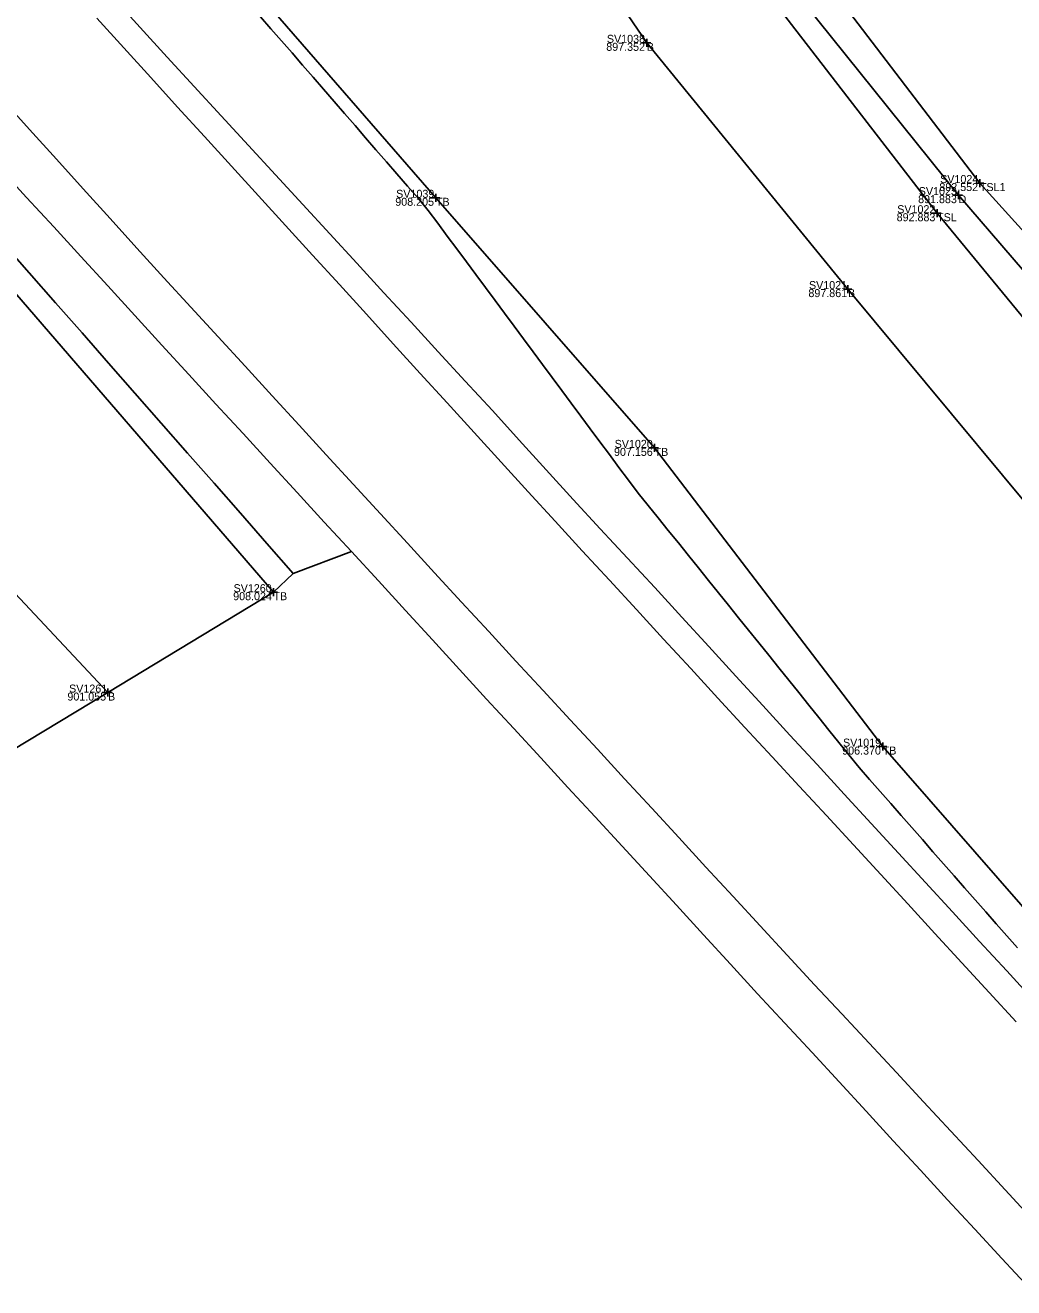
# Model space of a CAD drawing. Extents: x 1918148 to 1919797, y 624701 to 627089.
# Drawn here: x 1919035.3 to 1919158.7, y 625353.2 to 625511 of the extents above; entities that cross this region are included whole.
import ezdxf

# ---------------------------------------------------------------- set-up
doc = ezdxf.new("R2010")
doc.units = 0
for name, color, linetype in [('DR_X_Ditch', 7, 'Continuous'), ('DT_X_Terrain_Boundary', 7, 'Continuous'), ('PM_X_Edge_Line', 7, 'Continuous'), ('PV_X_Shoulder_Aggregate', 7, 'Continuous'), ('RD_X_Concrete_Pad', 7, 'Continuous'), ('SV_X_Break_Lines', 7, 'Continuous'), ('SV_X_Shot_Marker', 7, 'Continuous'), ('SV_X_Text_Comment', 7, 'Continuous'), ('SV_X_Text_Elevation', 7, 'Continuous'), ('SV_X_Text_Name', 7, 'Continuous'), ('SV_X_Toe_of_Slope', 7, 'Continuous'), ('SV_X_Top_of_Bank', 7, 'Continuous')]:
    doc.layers.add(name, color=color, linetype=linetype)

msp = doc.modelspace()

# ---------------------------------------------------------------- linework, layer by layer
at = {"layer": 'DR_X_Ditch'}
msp.add_lwpolyline([(1919219.02, 625407.66), (1919187.13, 625448.73), (1919151.86, 625489.75), (1919129.02, 625518.23), (1919101.03, 625555.91), (1919077.07, 625591.12), (1919056.34, 625619.29)], dxfattribs=at)
at = {"layer": 'DT_X_Terrain_Boundary'}
msp.add_lwpolyline([(1919029.61, 625417.96), (1919045.66, 625427.6), (1919066.32, 625440.14), (1919068.79, 625442.49), (1919076.05, 625445.23), (1919079.43, 625441.55), (1919082.8, 625437.86), (1919086.18, 625434.17), (1919089.55, 625430.48), (1919092.93, 625426.79), (1919096.31, 625423.11), (1919099.7, 625419.43), (1919103.08, 625415.75), (1919106.47, 625412.07), (1919109.86, 625408.4), (1919113.25, 625404.72), (1919116.63, 625401.04), (1919120.01, 625397.35), (1919123.38, 625393.66), (1919126.77, 625389.98), (1919130.16, 625386.31), (1919133.56, 625382.64), (1919136.95, 625378.97), (1919140.33, 625375.29), (1919143.71, 625371.6), (1919147.09, 625367.92), (1919150.49, 625364.24), (1919153.88, 625360.57), (1919157.27, 625356.9), (1919160.68, 625353.24)], dxfattribs=at)
at = {"layer": 'PM_X_Edge_Line'}
for points in [[(1919044.26, 625511.85), (1919047.62, 625508.15), (1919050.99, 625504.45), (1919054.35, 625500.75), (1919057.72, 625497.06), (1919061.08, 625493.36), (1919064.45, 625489.66), (1919067.82, 625485.97), (1919071.18, 625482.27), (1919074.55, 625478.57), (1919077.92, 625474.88), (1919081.28, 625471.18), (1919084.65, 625467.48), (1919088.02, 625463.79), (1919091.38, 625460.09), (1919094.75, 625456.39), (1919098.12, 625452.7), (1919101.49, 625449), (1919104.87, 625445.32), (1919108.26, 625441.64), (1919111.64, 625437.96), (1919115.03, 625434.28), (1919118.41, 625430.6), (1919121.8, 625426.92), (1919125.19, 625423.25), (1919128.58, 625419.58), (1919131.97, 625415.9), (1919135.37, 625412.23), (1919138.76, 625408.56), (1919142.15, 625404.88), (1919145.53, 625401.19), (1919148.9, 625397.51), (1919152.28, 625393.82), (1919155.66, 625390.14), (1919159.04, 625386.45)], [(1919032.51, 625501.67), (1919035.86, 625497.96), (1919039.21, 625494.24), (1919042.56, 625490.53), (1919045.91, 625486.82), (1919049.26, 625483.11), (1919052.64, 625479.43), (1919056.02, 625475.74), (1919059.4, 625472.06), (1919062.78, 625468.37), (1919066.16, 625464.68), (1919069.53, 625461), (1919072.91, 625457.31), (1919076.29, 625453.63), (1919079.67, 625449.94), (1919083.05, 625446.25), (1919086.43, 625442.57), (1919089.81, 625438.88), (1919093.2, 625435.21), (1919096.59, 625431.54), (1919099.98, 625427.86), (1919103.37, 625424.19), (1919106.76, 625420.51), (1919110.15, 625416.84), (1919113.54, 625413.16), (1919116.92, 625409.48), (1919120.31, 625405.8), (1919123.7, 625402.12), (1919127.08, 625398.44), (1919130.47, 625394.77), (1919133.88, 625391.1), (1919137.28, 625387.44), (1919140.68, 625383.78), (1919144.09, 625380.11), (1919147.49, 625376.45), (1919150.89, 625372.79), (1919154.29, 625369.12), (1919157.69, 625365.45), (1919161.08, 625361.78)]]:
    msp.add_lwpolyline(points, dxfattribs=at)
at = {"layer": 'PV_X_Shoulder_Aggregate'}
for points in [[(1919068.79, 625442.49), (1919065.49, 625446.24), (1919062.19, 625450), (1919058.9, 625453.75), (1919055.6, 625457.51), (1919052.3, 625461.26), (1919049.01, 625465.02), (1919045.71, 625468.77), (1919042.42, 625472.53), (1919039.12, 625476.29), (1919035.82, 625480.04), (1919032.53, 625483.8), (1919029.14, 625487.48), (1919025.75, 625491.14), (1919022.35, 625494.81), (1919018.95, 625498.47), (1919015.55, 625502.14), (1919012.16, 625505.8), (1919008.76, 625509.47), (1919005.36, 625513.13)], [(1919064.7, 625512.04), (1919066.01, 625510.53), (1919067.33, 625509.02), (1919068.64, 625507.51), (1919069.95, 625506), (1919071.26, 625504.49), (1919072.57, 625502.98), (1919073.88, 625501.47), (1919075.19, 625499.96), (1919076.5, 625498.44), (1919077.81, 625496.93), (1919079.12, 625495.42), (1919080.43, 625493.91), (1919081.74, 625492.4), (1919083.06, 625490.89), (1919084.37, 625489.38), (1919085.64, 625487.85), (1919086.83, 625486.24), (1919088.02, 625484.63), (1919089.21, 625483.03), (1919090.41, 625481.42), (1919091.6, 625479.82), (1919092.79, 625478.21), (1919093.98, 625476.6), (1919095.17, 625475), (1919096.36, 625473.39), (1919097.55, 625471.79), (1919098.74, 625470.18), (1919099.93, 625468.57), (1919101.12, 625466.97), (1919102.31, 625465.36), (1919103.5, 625463.75), (1919104.69, 625462.15), (1919105.88, 625460.54), (1919107.07, 625458.94), (1919108.26, 625457.33), (1919109.45, 625455.72), (1919110.64, 625454.12), (1919111.87, 625452.53), (1919113.12, 625450.98), (1919114.37, 625449.42), (1919115.62, 625447.86), (1919116.88, 625446.3), (1919118.13, 625444.74), (1919119.38, 625443.18), (1919120.64, 625441.62), (1919121.89, 625440.06), (1919123.14, 625438.51), (1919124.39, 625436.95), (1919125.65, 625435.39), (1919126.9, 625433.83), (1919128.15, 625432.27), (1919129.4, 625430.71), (1919130.66, 625429.15), (1919131.91, 625427.6), (1919133.16, 625426.04), (1919134.42, 625424.48), (1919135.67, 625422.92), (1919136.92, 625421.36), (1919138.17, 625419.8), (1919139.43, 625418.25), (1919140.75, 625416.75), (1919142.07, 625415.24), (1919143.39, 625413.74), (1919144.71, 625412.23), (1919146.02, 625410.73), (1919147.34, 625409.23), (1919148.66, 625407.72), (1919149.98, 625406.22), (1919151.3, 625404.71), (1919152.61, 625403.21), (1919153.93, 625401.71), (1919155.25, 625400.2), (1919156.57, 625398.7), (1919157.89, 625397.2), (1919159.2, 625395.69)]]:
    msp.add_lwpolyline(points, dxfattribs=at)
at = {"layer": 'RD_X_Concrete_Pad'}
for points in [[(1919046.34, 625514.42), (1919049.69, 625510.71), (1919053.05, 625507), (1919056.43, 625503.32), (1919059.81, 625499.64), (1919063.19, 625495.95), (1919066.58, 625492.28), (1919069.97, 625488.6), (1919073.36, 625484.92), (1919076.74, 625481.24), (1919080.12, 625477.56), (1919083.51, 625473.88), (1919086.89, 625470.19), (1919090.27, 625466.51), (1919093.65, 625462.83), (1919097.01, 625459.12), (1919100.36, 625455.41), (1919103.72, 625451.71), (1919107.12, 625448.04), (1919110.52, 625444.38), (1919113.92, 625440.71), (1919117.3, 625437.03), (1919120.68, 625433.34), (1919124.06, 625429.66), (1919127.44, 625425.97), (1919130.81, 625422.28), (1919134.19, 625418.6), (1919137.57, 625414.92), (1919140.96, 625411.23), (1919144.34, 625407.55), (1919147.72, 625403.87), (1919151.11, 625400.19), (1919154.49, 625396.51), (1919157.87, 625392.82), (1919161.25, 625389.13)], [(1919032.12, 625493.14), (1919035.49, 625489.45), (1919038.88, 625485.77), (1919042.27, 625482.1), (1919045.65, 625478.41), (1919049.01, 625474.71), (1919052.38, 625471.01), (1919055.75, 625467.32), (1919059.13, 625463.64), (1919062.52, 625459.96), (1919065.9, 625456.28), (1919069.28, 625452.6), (1919072.67, 625448.91), (1919076.05, 625445.23), (1919079.43, 625441.55), (1919082.8, 625437.86), (1919086.18, 625434.17), (1919089.55, 625430.48), (1919092.93, 625426.79), (1919096.31, 625423.11), (1919099.7, 625419.43), (1919103.08, 625415.75), (1919106.47, 625412.07), (1919109.86, 625408.4), (1919113.25, 625404.72), (1919116.63, 625401.04), (1919120.01, 625397.35), (1919123.38, 625393.66), (1919126.77, 625389.98), (1919130.16, 625386.31), (1919133.56, 625382.64), (1919136.95, 625378.97), (1919140.33, 625375.29), (1919143.71, 625371.6), (1919147.09, 625367.92), (1919150.49, 625364.24), (1919153.88, 625360.57), (1919157.27, 625356.9), (1919160.68, 625353.24)]]:
    msp.add_lwpolyline(points, dxfattribs=at)
at = {"layer": 'SV_X_Break_Lines'}
for points in [[(1919045.66, 625427.6), (1919011.53, 625464.07), (1918983.19, 625498.78), (1918965.77, 625524.18), (1918940.24, 625565.26), (1918931.64, 625587.04), (1918915.78, 625618.09), (1918902.81, 625643.72), (1918894.51, 625661.89), (1918884.61, 625712.49), (1918865.54, 625771.79)], [(1919206.86, 625400.05), (1919170.29, 625439.2), (1919138.05, 625478.01), (1919112.93, 625508.78), (1919087.56, 625546), (1919063.33, 625584.96), (1919048.27, 625604.54), (1919031.79, 625617.49), (1919020.42, 625620.88), (1919013.82, 625627.54), (1919010.2, 625639.42), (1919006.75, 625653.62), (1919000.26, 625672.97)]]:
    msp.add_lwpolyline(points, dxfattribs=at)
at = {"layer": 'SV_X_Shot_Marker'}
for p, q in [((1919112.93, 625509.28), (1919112.93, 625508.28)), ((1919112.43, 625508.78), (1919113.43, 625508.78)), ((1919112.93, 625508.78), (1919112.93, 625508.78)), ((1919154.52, 625491.76), (1919154.52, 625490.76)), ((1919151.86, 625490.25), (1919151.86, 625489.25)), ((1919154.02, 625491.26), (1919155.02, 625491.26)), ((1919154.52, 625491.26), (1919154.52, 625491.26)), ((1919086.1, 625489.42), (1919087.1, 625489.42)), ((1919086.6, 625489.92), (1919086.6, 625488.92)), ((1919086.6, 625489.42), (1919086.6, 625489.42)), ((1919151.36, 625489.75), (1919152.36, 625489.75)), ((1919151.86, 625489.75), (1919151.86, 625489.75)), ((1919148.68, 625487.49), (1919149.68, 625487.49)), ((1919149.18, 625487.99), (1919149.18, 625486.99)), ((1919149.18, 625487.49), (1919149.18, 625487.49)), ((1919137.55, 625478.01), (1919138.55, 625478.01)), ((1919138.05, 625478.51), (1919138.05, 625477.51)), ((1919138.05, 625478.01), (1919138.05, 625478.01)), ((1919113.9, 625458.67), (1919113.9, 625457.67)), ((1919113.4, 625458.17), (1919114.4, 625458.17)), ((1919113.9, 625458.17), (1919113.9, 625458.17)), ((1919065.82, 625440.14), (1919066.82, 625440.14)), ((1919066.32, 625440.64), (1919066.32, 625439.64)), ((1919066.32, 625440.14), (1919066.32, 625440.14)), ((1919045.16, 625427.6), (1919046.16, 625427.6)), ((1919045.66, 625428.1), (1919045.66, 625427.1)), ((1919045.66, 625427.6), (1919045.66, 625427.6)), ((1919141.89, 625420.85), (1919142.89, 625420.85)), ((1919142.39, 625421.35), (1919142.39, 625420.35)), ((1919142.39, 625420.85), (1919142.39, 625420.85))]:
    msp.add_line(p, q, dxfattribs=at)
at = {"layer": 'SV_X_Toe_of_Slope'}
for points in [[(1919222.3, 625409.72), (1919190.71, 625451.22), (1919154.52, 625491.26), (1919132.35, 625520.35), (1919103.41, 625557.58), (1919078.28, 625592.14), (1919056.75, 625620.59)], [(1919214.66, 625404.51), (1919183.35, 625445.99), (1919149.18, 625487.49), (1919126.62, 625516.79), (1919098.28, 625553.96), (1919075.71, 625589.98), (1919054.68, 625616.82)]]:
    msp.add_lwpolyline(points, dxfattribs=at)
at = {"layer": 'SV_X_Top_of_Bank'}
for points in [[(1919180.03, 625377.77), (1919142.39, 625420.85), (1919113.9, 625458.17), (1919086.6, 625489.42), (1919057.39, 625523.08), (1919019.76, 625570.22), (1918998.07, 625602.27), (1918985.26, 625627.56), (1918968.39, 625668.03), (1918955.62, 625707.63), (1918947.9, 625739.17), (1918945.04, 625765.59), (1918947.37, 625785.94), (1918957.93, 625802.75), (1918975.61, 625809.21), (1918997.58, 625813.39), (1919030.67, 625814.44), (1919065.45, 625812.35), (1919111.29, 625808.54)], [(1919066.32, 625440.14), (1919029.78, 625482.47), (1919003.4, 625512.19), (1918983.32, 625538.26), (1918960.17, 625575.62), (1918948.94, 625596.56), (1918932.63, 625627.72), (1918922.22, 625652.79), (1918916.09, 625672.67), (1918901.24, 625716.64), (1918882.07, 625777.61)]]:
    msp.add_lwpolyline(points, dxfattribs=at)

# ---------------------------------------------------------------- texts
at = {"layer": 'SV_X_Text_Comment'}
for s, p in [('B', (1919112.93, 625507.78)), ('TSL1', (1919154.52, 625490.26)), ('TB', (1919086.6, 625488.42)), ('D', (1919151.86, 625488.75)), ('TSL', (1919149.18, 625486.49)), ('B', (1919138.05, 625477.01)), ('TB', (1919113.9, 625457.17)), ('TB', (1919066.32, 625439.14)), ('B', (1919045.66, 625426.6)), ('TB', (1919142.39, 625419.85))]:
    msp.add_text(s, height=1, dxfattribs=at).set_placement(p)
at = {"layer": 'SV_X_Text_Elevation'}
for s, p in [('897.352', (1919107.87, 625507.78)), ('892.552', (1919149.46, 625490.26)), ('908.205', (1919081.53, 625488.42)), ('891.883', (1919146.81, 625488.75)), ('892.883', (1919144.13, 625486.49)), ('897.861', (1919133.11, 625477.01)), ('907.156', (1919108.84, 625457.17)), ('908.024', (1919061.29, 625439.14)), ('901.055', (1919040.59, 625426.6)), ('906.370', (1919137.33, 625419.85))]:
    msp.add_text(s, height=1, dxfattribs=at).set_placement(p)
at = {"layer": 'SV_X_Text_Name'}
for s, p in [('SV1038', (1919107.95, 625508.78)), ('SV1024', (1919149.56, 625491.26)), ('SV1039', (1919081.64, 625489.42)), ('SV1023', (1919146.89, 625489.75)), ('SV1022', (1919144.2, 625487.49)), ('SV1021', (1919133.18, 625478.01)), ('SV1020', (1919108.92, 625458.17)), ('SV1260', (1919061.34, 625440.14)), ('SV1261', (1919040.8, 625427.6)), ('SV1019', (1919137.43, 625420.85))]:
    msp.add_text(s, height=1, dxfattribs=at).set_placement(p)

doc.saveas('drawing.dxf')
